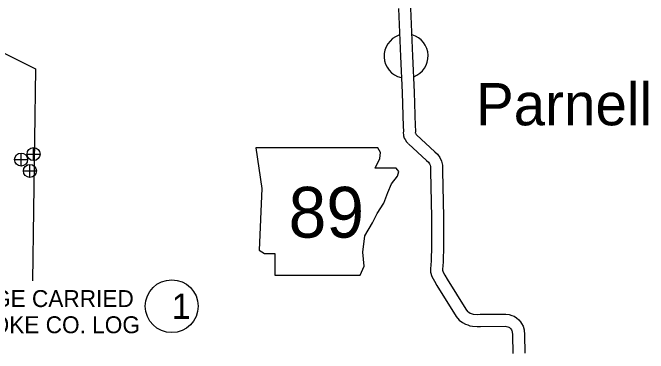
# Model space of a CAD drawing. Extents: x 1127717 to 1741049, y 2026793 to 2244711.
# Drawn here: x 1248173 to 1256105, y 2146423 to 2150676 of the extents above; entities that cross this region are included whole.
import ezdxf

# ---------------------------------------------------------------- set-up
doc = ezdxf.new("R2010")
doc.units = 0
for name, color, linetype in [('10', 7, 'Continuous'), ('21', 7, 'Continuous'), ('24', 7, 'Continuous'), ('26', 7, 'Continuous'), ('27', 7, 'Continuous'), ('30', 7, 'Continuous')]:
    doc.layers.add(name, color=color, linetype=linetype)

msp = doc.modelspace()

# ---------------------------------------------------------------- linework, layer by layer
at = {"layer": '10'}
for points in [[(1252988.2, 2150726.7), (1253014, 2150127.8), (1253033.8, 2149678.1), (1253044.8, 2149250.5), (1253048.5, 2149206), (1253048.4, 2149196.1), (1253047, 2149174.2), (1253049.1, 2149153.3), (1253051.5, 2149140), (1253060.5, 2149109.4), (1253072.9, 2149091.9), (1253087.4, 2149065.5), (1253110.4, 2149042.6)], [(1253138, 2150734.5), (1253163.8, 2150134.4), (1253183.7, 2149683.3), (1253194.6, 2149258.8), (1253198.6, 2149211.4), (1253198.4, 2149190.2), (1253197.5, 2149177), (1253197.7, 2149175.3), (1253200.3, 2149171.6), (1253208.6, 2149156.5), (1253216.2, 2149148.9)], [(1253214.4, 2149150.7), (1253440.4, 2148940.5), (1253472.5, 2148909), (1253504.1, 2148868.1), (1253525.8, 2148824.2), (1253537.4, 2148771.8), (1253538.9, 2148702.2), (1253547.6, 2148122.3), (1253550.4, 2147759.4), (1253545.3, 2147570.8), (1253539, 2147511.1), (1253537.7, 2147479.9), (1253538, 2147459.9), (1253544.3, 2147437.7), (1253565.3, 2147397.7), (1253595.4, 2147349.2), (1253827.4, 2146972.5), (1253848.8, 2146947.2), (1253865.9, 2146934.9), (1253881.9, 2146926), (1253908.8, 2146917.4), (1253918.9, 2146912.4), (1253922.6, 2146912.1), (1253974.1, 2146909.4), (1254008.9, 2146910), (1254325.6, 2146911.8), (1254368.5, 2146907), (1254400.7, 2146897), (1254430.5, 2146886.1), (1254460.1, 2146867), (1254491.3, 2146842), (1254510.6, 2146815.8), (1254524.9, 2146795.4), (1254543.9, 2146762.9), (1254555.6, 2146716.3), (1254559.1, 2146654.8), (1254566.4, 2146424)], [(1253112.2, 2149040.8), (1253336.8, 2148832), (1253360.2, 2148809.1), (1253376.3, 2148788.3), (1253383.3, 2148774.1), (1253387.8, 2148753.8), (1253389, 2148699.4), (1253397.7, 2148120.6), (1253400.4, 2147760.8), (1253395.5, 2147580.7), (1253389.3, 2147521.9), (1253387.7, 2147481.9), (1253388.3, 2147437.9), (1253404.3, 2147381.7), (1253435.1, 2147323.1), (1253467.9, 2147270.3), (1253705.6, 2146884.2), (1253746.2, 2146836.3), (1253785.2, 2146808.2), (1253822, 2146787.7), (1253852.5, 2146777.9), (1253876.8, 2146765.9), (1253911.2, 2146762.4), (1253971.6, 2146759.4), (1254010.6, 2146760), (1254317.5, 2146761.8), (1254337.7, 2146759.5), (1254352.8, 2146754.8), (1254363.3, 2146751), (1254372.4, 2146745.1), (1254382.1, 2146737.3), (1254388.8, 2146728.3), (1254398.5, 2146714.4), (1254403.6, 2146705.6), (1254406.7, 2146693.5), (1254409.3, 2146648.1), (1254416.4, 2146419.3)]]:
    msp.add_lwpolyline(points, dxfattribs=at)
at = {"layer": '21'}
msp.add_lwpolyline([(1251207.1, 2148989.6), (1251283.2, 2148482.1), (1251249.3, 2147712.3), (1251317, 2147670), (1251443.9, 2147670), (1251443.9, 2147399.3), (1252509.7, 2147399.3), (1252560.5, 2147509.3), (1252543.6, 2147686.9), (1252568.9, 2147889.9), (1252662, 2148050.7), (1252721.2, 2148169.1), (1252805.8, 2148296), (1252856.6, 2148431.3), (1252898.8, 2148541.3), (1252975, 2148634.3), (1252991.9, 2148693.5), (1252958.1, 2148735.8), (1252695.8, 2148735.8), (1252755, 2148854.3), (1252763.5, 2148930.4), (1252728.4, 2148988.9)], close=True, dxfattribs=at)
at = {"layer": '24'}
for start, end in [(109.01367, 256.82016), (290.4723, 73.95574)]:
    msp.add_arc((1253082.5, 2150134.8), 275, start, end, dxfattribs=at)
at = {"layer": '26'}
for p, q in [((1248432.6, 2148829.9), (1248432.6, 2148992.4)), ((1248277.9, 2148761.2), (1248277.9, 2148923.7)), ((1248196.6, 2148842.4), (1248359.1, 2148842.4)), ((1248351.4, 2148911.1), (1248513.9, 2148911.1)), ((1248387.6, 2148618.5), (1248387.6, 2148781)), ((1248306.4, 2148699.8), (1248468.9, 2148699.8))]:
    msp.add_line(p, q, dxfattribs=at)
for centre in [(1248432.6, 2148911.1), (1248277.9, 2148842.4), (1248387.6, 2148699.8)]:
    msp.add_circle(centre, 81.2, dxfattribs=at)
at = {"layer": '27'}
msp.add_circle((1250157.6, 2147011.1), 330, dxfattribs=at)
at = {"layer": '30'}
for p, q in [((1247532.8, 2150437.7), (1248457.1, 2149975.5)), ((1248457.1, 2149975.5), (1248421.5, 2147327.1))]:
    msp.add_line(p, q, dxfattribs=at)

# ---------------------------------------------------------------- texts
at = {"layer": '21'}
msp.add_text('89', height=633.6, dxfattribs=at).set_placement((1251615.6, 2147867.9))
at = {"layer": '24'}
msp.add_text('Parnell', height=528, dxfattribs=at).set_placement((1253954.6, 2149270.2))
at = {"layer": '27'}
msp.add_text('1', height=316.8, dxfattribs=at).set_placement((1250157.6, 2146852.7))
at = {"layer": '30'}
for s, p in [('MILEAGE CARRIED', (1247078.9, 2147001.1)), ('ON LONOKE CO. LOG', (1246826.7, 2146674.2))]:
    msp.add_text(s, height=211.2, dxfattribs=at).set_placement(p)

doc.saveas('drawing.dxf')
